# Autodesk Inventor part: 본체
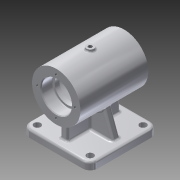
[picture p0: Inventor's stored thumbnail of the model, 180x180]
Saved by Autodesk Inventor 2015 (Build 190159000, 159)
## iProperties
Created: 2019-06
Part Number: 본체
Material: 알루미늄 6061
Document SubType Name: Modeling
Designer: a-20
Density: 2.7 g/cm^3
Appearance: 알루미늄 - 평지
Mass: 610.332 g
Surface Area: 621.752 cm^2
Volume: 226.049 cm^3
Author: a-20
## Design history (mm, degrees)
sketch "스케치1"
  geometry: L1 (-45, 45)-(45, 45); L2 (45, 45)-(45, -45); L3 (45, -45)-(-45, -45); L4 (-45, -45)-(-45, 45); 3 further points
  constraints: 8 end point, 2 midpoint, 2 parallel, 1 horizontal, 1 perpendicular, 1 vertical alignment
  dimensions: "d0" = 90 distance between parallel lines of L3 L1; "d1" = 90 distance between parallel lines of L2 L4; "d2" = 45 distance from line of point (0, 0) L1
extrude "돌출1" new body sketch "스케치1" distance "d3" = 10; taper "d4" = 0 deg
node "작업 평면1"
sketch "스케치2"
  geometry: L1 (0, 0)-(0, -45); L2 (0, -45)-(32, -45); L3 (-45, -45)-(45, -45) reference; L4 (32, -45)-(32, 45); L5 (45, 45)-(-45, 45) reference; L6 (0, 0)-(0, 45); L7 (0, 45)-(20, 45); L8 (32, 45)-(20, 45); L9 (20, 45)-(20, 30); L10 (20, 45)-(32, 45); L11 (20, 30)-(17, 30); L12 (17, 30)-(17, 24); L13 (17, 24)-(25, 24); L14 (25, 24)-(25, -24); L15 (25, -24)-(17, -24); L16 (17, -24)-(17, -30); L17 (17, -30)-(20, -30); L18 (20, -30)-(20, -45); L19 (20, -45)-(32, -45)
  constraints: 34 end point, 7 perpendicular, 4 point on line, 2 horizontal, 2 vertical, 1 collinear, 1 midpoint
  dimensions: "d6" = 45 distance of L1.start L1.end; "d7" = 32 distance of L1.end L2.end; "d8" = 90 distance of L2.end L4.end; "d9" = 20 distance of L6.end L7.end; "d10" = 15 distance of L7.end L9.end; "d11" = 3 distance of L9.end L11.end; "d12" = 6 distance of L11.end L12.end; "d13" = 8 distance of L12.end L13.end; "d14" = 48 distance of L13.end L14.end; "d15" = 90 deg angle of L13 L14 (derived); "d16" = 8 distance of L14.end L15.end; "d17" = 6 distance of L15.end L16.end; "d18" = 90 deg angle of L16 L15 (derived); "d19" = 3 distance of L16.end L17.end
revolve "회전1" sketch "스케치2" stored, may be unused: angle "d20" = 90 deg
sketch "스케치3"
  geometry: L1 (-5, 35)-(5, 35); L2 (5, 35)-(5, -35); L3 (5, -35)-(-5, -35); L4 (-5, -35)-(-5, 35); 1 further point
  constraints: 8 end point, 2 parallel, 1 horizontal, 1 perpendicular
  dimensions: "d21" = 5 distance from line of point (0, 0) L4; "d22" = 5 distance from line of point (0, 0) L2; "d23" = 35 distance from line of point (0, 0) L1; "d24" = 35 distance from line of L3 point (0, 0)
extrude "돌출2" join sketch "스케치3" stored distance "d25" = 10; taper "d26" = 0 deg
sketch "스케치6"
  geometry: L1 (35, 10)-(23.058, 42.811); L2 (45, 0)-(45, 10) reference; 1 further point
  constraints: 2 end point
  dimensions: "d46" = 36.30944 distance from line of point (0, 0) L1; "d47" = 36.40055 distance of point (0, 0) L1.start; "d48" = 48.62568 distance of point (0, 0) L1.end; "d49" = 10 distance from line of L1.start L2
feature "리브1" sketch "스케치6" dims "d40" = 1, "d41" = 10, "d42" = 0, "d43" = 0, "d44" = 1, "d45" = 1
fillet "모깎기1" dims "d50" = 10
sketch "스케치7"
  geometry: L1 (35, 45)-(-35, 45) reference; L2 (-45, 35)-(-45, -35) reference; L3 (-35, -45)-(35, -45) reference; L4 (45, -35)-(45, 35) reference; L5 (-35, -5)-(-35, 5) reference; L6 (-35, 5)-(-5, 5) reference; L7 (-5, 5)-(-5, 35) reference; L8 (-5, 35)-(5, 35) reference; L9 (5, 35)-(5, 5) reference; L10 (5, 5)-(35, 5) reference; L11 (35, 5)-(35, -5) reference; L12 (35, -5)-(5, -5) reference; L13 (5, -5)-(5, -35) reference; L14 (5, -35)-(-5, -35) reference; L15 (-5, -35)-(-5, -5) reference; L16 (-5, -5)-(-35, -5) reference; A1 r 10 centre (35, 35) between (45, 35) and (35, 45) reference; A2 r 10 centre (-35, 35) between (-35, 45) and (-45, 35) reference; A3 r 10 centre (-35, -35) between (-45, -35) and (-35, -45) reference; A4 r 10 centre (35, -35) between (35, -45) and (45, -35) reference; 1 further point
hole "구멍1" sketch "스케치7" at (-35, -35), (-35, 35), (35, 35), (35, -35) diameter "d51" = 9; stored, may be unused: countersink angle "d55" = 90 deg, drill point angle "d57" = 118 deg; dims "d52" = 6, "d53" = 4, "d54" = 2, "d56" = 10
fillet "모깎기2" dims "d58" = 3
node "작업 평면2"
sketch "스케치8"
  geometry: C1 r 5 at (0, 0); 1 further point
  constraints: 1 centre point, 1 coincident
  dimensions: "d60" = 10 diameter of C1
extrude "돌출4" join sketch "스케치8" stored distance "d61" = 10; taper "d62" = 0 deg
fillet "모깎기3" dims "d63" = 2
sketch "스케치9"
  geometry: C1 r 5 at (0, 0) reference; 1 further point
hole "구멍2" sketch "스케치9" at (0, 0) diameter "d64" = 4.917; stored, may be unused: countersink angle "d68" = 90 deg, drill point angle "d70" = 118 deg; dims "d65" = 12, "d66" = 4, "d67" = 2, "d69" = 17.1
sketch "스케치12"
  geometry: C1 r 17 at (0, 0) reference; 2 further points
  dimensions: "d82" = 25 distance of point (0, -25) C1.centre; "d83" = 90 distance of point (0, 65) point (0, -25)
hole "구멍4" sketch "스케치12" at (0, -25) diameter "d84" = 3.242; stored, may be unused: countersink angle "d88" = 90 deg, drill point angle "d90" = 118 deg; dims "d85" = 7, "d86" = 4, "d87" = 2, "d89" = 9
sketch "스케치13"
  geometry: L1 (-26.34, -40)-(26.34, -40); L2 (40, -26.34)-(40, 26.34); L3 (26.34, 40)-(-26.34, 40); L4 (-40, 26.34)-(-40, -26.34); A1 r 10 centre (-35, -35) between (-45, -35) and (-35, -45) reference; A2 r 10 centre (-35, 35) between (-35, 45) and (-45, 35) reference; A3 r 10 centre (35, 35) between (45, 35) and (35, 45) reference; A4 r 10 centre (35, -35) between (35, -45) and (45, -35) reference; A5 r 10 centre (-35, -35) between (-26.34, -40) and (-40, -26.34); A6 r 10 centre (-35, 35) between (-40, 26.34) and (-26.34, 40); A7 r 10 centre (35, -35) between (40, -26.34) and (26.34, -40); A8 r 10 centre (35, 35) between (26.34, 40) and (40, 26.34); 1 further point
  constraints: 8 end point, 8 point on circle, 4 centre point, 4 coincident, 2 parallel, 1 horizontal, 1 perpendicular
  dimensions: "d94" = 40 distance from line of point (0, 0) L4; "d96" = 80 distance between parallel lines of L4 L2; "d97" = 40 distance from line of point (0, 0) L1; "d98" = 80 distance between parallel lines of L3 L1; "d99" = 20 diameter of A5; "d100" = 20 diameter of A6; "d101" = 20 diameter of A7; "d102" = 20 diameter of A8
extrude "돌출5" cut sketch "스케치13" distance "d103" = 5; taper "d104" = 0 deg
fillet "모깎기4" dims "d105" = 3
fillet "모깎기5" dims "d106" = 0.6
fillet "모깎기6" dims "d107" = 3
chamfer "모따기1" distance "d108" = 1; stored, may be unused: second distance "d109" = 2, angle "d110" = 45 deg
sketch "스케치14"
  geometry: L1 (7, 80)-(0, 80) reference; 2 further points
  constraints: 1 other
  dimensions: "d111" = 45 distance from line of point (4, 35) L1; "d112" = 4 distance of point (0, 35) point (4, 35)
feature "엠보싱1" sketch "스케치14" dims "d0" = 90, "d1" = 90, "d2" = 45, "d113" = 0.5, "d114" = 0
node "솔리드1"
mirror "대칭1"
pattern_circular "원형 패턴1" dims angle "d92" = 360 deg
mirror "대칭2"
node "투영된 루프1"
node "투영된 루프2"
other parameters: "d5" = 55
